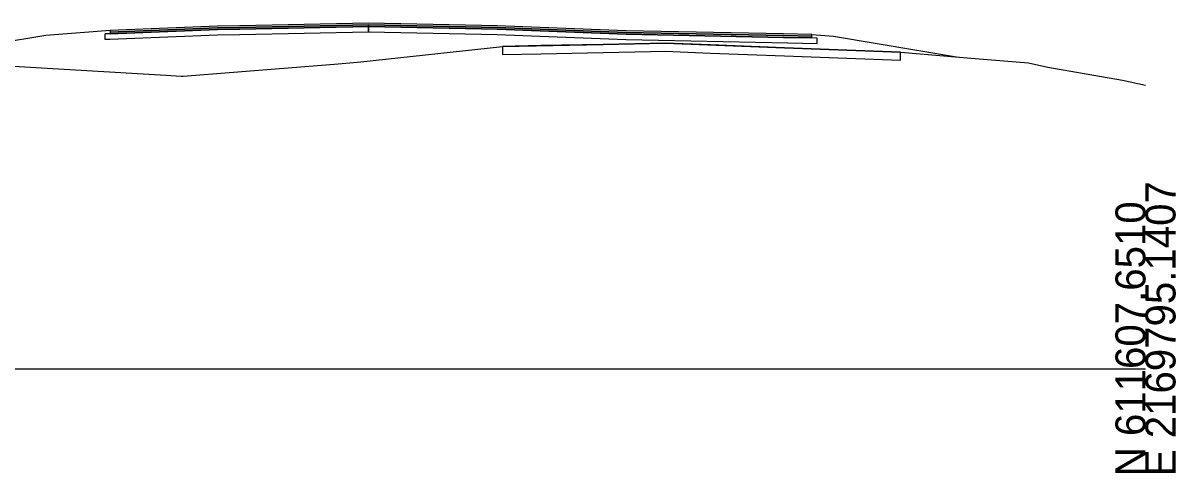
# Model space of a CAD drawing. Extents: x -26 to 1303, y -3010 to 12038.
# Drawn here: x 1195.4 to 1302.8, y 2990.3 to 3032.2 of the extents above; entities that cross this region are included whole.
import ezdxf

# ---------------------------------------------------------------- set-up
doc = ezdxf.new("R2010")
doc.units = 0
for name, color, linetype in [('RD_GPK_XS_Cell', 7, 'Continuous'), ('RD_XS_Base', 7, 'Continuous'), ('RD_XS_ExGround', 7, 'Continuous'), ('RD_XS_ExPaveRet', 7, 'Continuous'), ('RD_XS_Greenside', 7, 'Continuous'), ('RD_XS_Pave', 7, 'Continuous'), ('RD_XS_PaveOvlay_CP', 7, 'Continuous'), ('RD_XS_TieSlope', 7, 'Continuous')]:
    doc.layers.add(name, color=color, linetype=linetype)

msp = doc.modelspace()

# ---------------------------------------------------------------- linework, layer by layer
at = {"layer": 'RD_GPK_XS_Cell'}
msp.add_line((1150, 3000), (1300, 3000), dxfattribs=at)
at = {"layer": 'RD_XS_Base'}
for p, q in [((1213.53, 3031.61), (1204.28, 3031.24)), ((1215.61, 3031.66), (1213.53, 3031.61)), ((1227.61, 3031.9), (1215.61, 3031.66)), ((1215.61, 3031.16), (1227.61, 3031.4)), ((1227.61, 3031.91), (1227.61, 3032.05)), ((1227.61, 3032.05), (1227.61, 3031.47)), ((1227.61, 3031.9), (1227.61, 3031.91)), ((1227.61, 3031.9), (1227.61, 3031.9)), ((1238.15, 3031.68), (1227.61, 3031.9)), ((1227.61, 3031.9), (1227.61, 3031.9)), ((1227.61, 3031.45), (1227.61, 3031.9)), ((1227.61, 3031.47), (1227.61, 3031.4)), ((1227.61, 3031.4), (1227.61, 3031.45)), ((1227.61, 3031.4), (1238.15, 3031.18)), ((1239.61, 3031.66), (1238.15, 3031.68)), ((1250, 3031.24), (1239.61, 3031.66)), ((1203.07, 3031.2), (1203.03, 3031.19)), ((1203.03, 3031.19), (1203.03, 3030.73)), ((1203.03, 3030.73), (1203.03, 3030.69)), ((1203.03, 3030.69), (1203.07, 3030.7)), ((1203.53, 3031.21), (1203.07, 3031.2)), ((1203.07, 3030.7), (1203.53, 3030.71)), ((1204.28, 3031.24), (1203.53, 3031.21)), ((1203.53, 3030.71), (1204.28, 3030.74)), ((1204.28, 3030.74), (1213.53, 3031.11)), ((1213.53, 3031.11), (1215.61, 3031.16)), ((1238.15, 3031.18), (1239.61, 3031.16)), ((1239.61, 3031.16), (1250, 3030.74)), ((1251.62, 3031.18), (1250, 3031.24)), ((1250, 3030.74), (1251.62, 3030.68)), ((1266.28, 3030.88), (1251.62, 3031.18)), ((1251.62, 3030.68), (1266.69, 3030.37)), ((1268.92, 3030.83), (1266.28, 3030.88)), ((1266.69, 3030.37), (1269.42, 3030.32)), ((1269.34, 3030.82), (1268.92, 3030.83)), ((1269.42, 3030.82), (1269.34, 3030.82)), ((1269.42, 3030.4), (1269.42, 3030.82)), ((1269.42, 3030.32), (1269.42, 3030.4))]:
    msp.add_line(p, q, dxfattribs=at)
at = {"layer": 'RD_XS_ExGround'}
msp.add_lwpolyline([(1192.38, 3028.32), (1208.74, 3027.37), (1210.14, 3027.28), (1210.34, 3027.28), (1224.42, 3028.39), (1225.88, 3028.5), (1226.89, 3028.61), (1240.09, 3030.04), (1249.46, 3030.23), (1255.26, 3030.34), (1266.38, 3029.91), (1277.18, 3029.51), (1284.14, 3028.91), (1289.11, 3028.52), (1290.9, 3028.1), (1297.85, 3026.88), (1300, 3026.44)], dxfattribs=at)
at = {"layer": 'RD_XS_ExPaveRet'}
for p, q in [((1253.89, 3030.31), (1249.46, 3030.23)), ((1243.65, 3030.11), (1240.09, 3030.04)), ((1249.46, 3030.23), (1243.65, 3030.11)), ((1277.18, 3029.2), (1277.18, 3029.51))]:
    msp.add_line(p, q, dxfattribs=at)
for points in [[(1266.38, 3029.91), (1259.47, 3030.17), (1255.26, 3030.34), (1253.89, 3030.31), (1249.46, 3030.23), (1243.65, 3030.11), (1240.09, 3030.04), (1240.09, 3030.04), (1240.09, 3030.04), (1240.09, 3029.62), (1240.09, 3029.29), (1240.09, 3029.29), (1240.09, 3029.29), (1243.65, 3029.36), (1249.46, 3029.48), (1253.89, 3029.56), (1255.26, 3029.59), (1259.47, 3029.42), (1266.38, 3029.16), (1272.18, 3028.94), (1277.18, 3028.76), (1277.18, 3029.2), (1277.18, 3029.51), (1272.18, 3029.69), (1266.38, 3029.91)], [(1266.38, 3029.91), (1259.47, 3030.17), (1255.26, 3030.34), (1253.89, 3030.31)], [(1240.09, 3030.04), (1240.09, 3029.62), (1240.09, 3029.29), (1243.65, 3029.36), (1249.46, 3029.48), (1253.89, 3029.56), (1255.26, 3029.59), (1259.47, 3029.42), (1266.38, 3029.16), (1272.18, 3028.94), (1277.18, 3028.76), (1277.18, 3029.2)], [(1277.18, 3029.51), (1272.18, 3029.69), (1266.38, 3029.91)]]:
    msp.add_lwpolyline(points, dxfattribs=at)
at = {"layer": 'RD_XS_Greenside'}
for p, q in [((1197.53, 3031.05), (1186.85, 3029.27)), ((1270.92, 3030.99), (1282.58, 3029.04))]:
    msp.add_line(p, q, dxfattribs=at)
at = {"layer": 'RD_XS_Pave'}
for p, q in [((1204.28, 3031.56), (1203.53, 3031.53)), ((1203.53, 3031.53), (1203.53, 3031.38)), ((1204.28, 3031.4), (1203.53, 3031.37)), ((1203.53, 3031.37), (1204.28, 3031.4)), ((1203.53, 3031.38), (1203.53, 3031.37)), ((1203.53, 3031.37), (1203.53, 3031.23)), ((1213.53, 3031.93), (1204.28, 3031.56)), ((1213.53, 3031.77), (1204.28, 3031.4)), ((1204.28, 3031.4), (1213.53, 3031.77)), ((1204.28, 3031.24), (1213.53, 3031.61)), ((1215.61, 3031.97), (1213.53, 3031.93)), ((1215.61, 3031.81), (1213.53, 3031.77)), ((1213.53, 3031.77), (1215.61, 3031.81)), ((1213.53, 3031.61), (1215.61, 3031.66)), ((1227.61, 3032.21), (1215.61, 3031.97)), ((1227.61, 3032.05), (1215.61, 3031.81)), ((1215.61, 3031.81), (1227.61, 3032.05)), ((1215.61, 3031.66), (1227.61, 3031.9)), ((1238.15, 3032), (1227.61, 3032.21)), ((1227.61, 3031.91), (1227.61, 3032.05)), ((1227.61, 3032.05), (1238.15, 3031.84)), ((1238.15, 3031.84), (1227.61, 3032.05)), ((1227.61, 3032.05), (1227.61, 3032.05)), ((1227.61, 3032.05), (1227.61, 3032.05)), ((1227.61, 3032.05), (1227.61, 3031.91)), ((1227.61, 3031.9), (1227.61, 3031.91)), ((1227.61, 3031.91), (1227.61, 3031.9)), ((1227.61, 3031.9), (1227.61, 3031.9)), ((1227.61, 3031.9), (1227.61, 3031.9)), ((1227.61, 3031.9), (1238.15, 3031.68)), ((1239.61, 3031.97), (1238.15, 3032)), ((1238.15, 3031.84), (1239.61, 3031.81)), ((1239.61, 3031.81), (1238.15, 3031.84)), ((1238.15, 3031.68), (1239.61, 3031.66)), ((1250, 3031.56), (1239.61, 3031.97)), ((1239.61, 3031.81), (1250, 3031.4)), ((1250, 3031.4), (1239.61, 3031.81)), ((1239.61, 3031.66), (1250, 3031.24)), ((1251.62, 3031.49), (1250, 3031.56)), ((1250, 3031.4), (1251.62, 3031.33)), ((1251.62, 3031.33), (1250, 3031.4)), ((1266.28, 3031.2), (1251.62, 3031.49)), ((1203.53, 3031.21), (1204.28, 3031.24)), ((1203.53, 3031.23), (1203.53, 3031.21)), ((1250, 3031.24), (1251.62, 3031.18)), ((1251.62, 3031.33), (1266.28, 3031.04)), ((1266.28, 3031.04), (1251.62, 3031.33)), ((1251.62, 3031.18), (1266.28, 3030.88)), ((1268.92, 3031.15), (1266.28, 3031.2)), ((1266.28, 3031.04), (1268.92, 3030.99)), ((1268.92, 3030.99), (1266.28, 3031.04)), ((1266.28, 3030.88), (1268.92, 3030.83)), ((1268.92, 3031.01), (1268.92, 3031.15)), ((1268.92, 3030.99), (1268.92, 3031.01)), ((1268.92, 3030.85), (1268.92, 3030.99)), ((1268.92, 3030.83), (1268.92, 3030.85))]:
    msp.add_line(p, q, dxfattribs=at)
at = {"layer": 'RD_XS_PaveOvlay_CP'}
for p, q in [((1204.28, 3031.56), (1203.53, 3031.53)), ((1213.53, 3031.93), (1204.28, 3031.56)), ((1215.61, 3031.97), (1213.53, 3031.93)), ((1227.61, 3032.21), (1215.61, 3031.97)), ((1238.15, 3032), (1227.61, 3032.21)), ((1239.61, 3031.97), (1238.15, 3032)), ((1250, 3031.56), (1239.61, 3031.97)), ((1251.62, 3031.49), (1250, 3031.56)), ((1266.28, 3031.2), (1251.62, 3031.49)), ((1268.92, 3031.15), (1266.28, 3031.2))]:
    msp.add_line(p, q, dxfattribs=at)
at = {"layer": 'RD_XS_TieSlope'}
for p, q in [((1203.53, 3031.53), (1197.53, 3031.05)), ((1268.92, 3031.15), (1270.92, 3030.99))]:
    msp.add_line(p, q, dxfattribs=at)

# ---------------------------------------------------------------- texts
at = {"layer": 'RD_GPK_XS_Cell'}
for s, p in [('E 2169795.1407', (1302.8, 2990)), ('N 611607.6510', (1300, 2990))]:
    msp.add_text(s, height=2.8, rotation=90, dxfattribs=at).set_placement(p)

doc.saveas('drawing.dxf')
